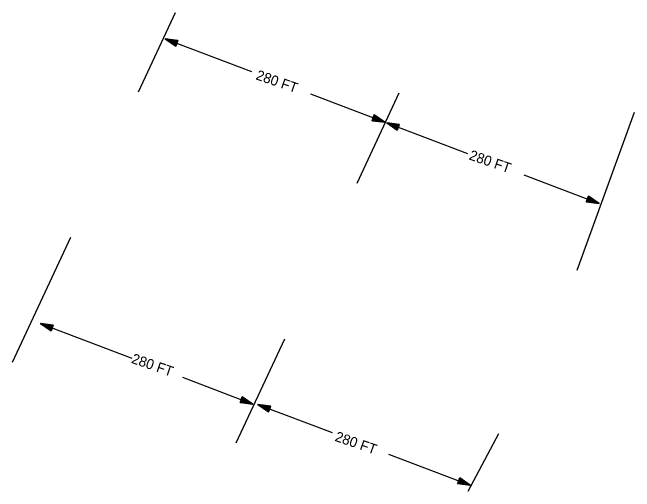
# Model space of a CAD drawing. Extents: x 1638506 to 1658005, y 834807 to 846788.
# Drawn here: x 1638846 to 1639584, y 840006 to 840574 of the extents above; entities that cross this region are included whole.
import ezdxf

# ---------------------------------------------------------------- set-up
doc = ezdxf.new("R2010")
doc.units = 0
doc.layers.add('Default', color=7, linetype='Continuous')

msp = doc.modelspace()

# ---------------------------------------------------------------- linework, layer by layer
at = {"layer": 'Default'}
for p, q in [((1638995.77, 840480.13), (1639039.69, 840574.45)), ((1639027.46, 840542.98), (1639129.82, 840504.15)), ((1639199.65, 840477.66), (1639287.86, 840444.19)), ((1639255.18, 840371.66), (1639305.11, 840478.9)), ((1639516.11, 840268.32), (1639584.12, 840455.99)), ((1639290.17, 840443.32), (1639386.13, 840406.91)), ((1639452.93, 840381.57), (1639542.02, 840347.78)), ((1638846.32, 840159.16), (1638915.51, 840307.75)), ((1638879.63, 840205.15), (1638987.93, 840164.07)), ((1639111.75, 840063.61), (1639169.28, 840187.17)), ((1639047.89, 840141.32), (1639131.48, 840109.61)), ((1639137.47, 840108.98), (1639225.32, 840075.66)), ((1639422.88, 840074.06), (1639386.35, 840005.71)), ((1639292.23, 840050.27), (1639389.31, 840013.44))]:
    msp.add_line(p, q, dxfattribs=at)
for points in [[(1639041.29, 840537.73), (1639041.03, 840537.04), (1639027.46, 840542.98), (1639040.78, 840536.39), (1639040.52, 840535.7), (1639027.46, 840542.98), (1639040.26, 840535.01), (1639040, 840534.32), (1639027.46, 840542.98), (1639042.56, 840541.21), (1639042.34, 840540.5), (1639027.46, 840542.98), (1639042.03, 840539.82), (1639041.82, 840539.11), (1639027.46, 840542.98), (1639041.55, 840538.42), (1639040, 840534.32), (1639042.56, 840541.21), (1639027.46, 840542.98), (1639040, 840534.32)], [(1639274.03, 840449.44), (1639274.29, 840450.13), (1639287.86, 840444.19), (1639274.54, 840450.78), (1639274.8, 840451.47), (1639287.86, 840444.19), (1639275.06, 840452.16), (1639275.32, 840452.85), (1639287.86, 840444.19), (1639272.76, 840445.96), (1639272.98, 840446.67), (1639287.86, 840444.19), (1639273.29, 840447.35), (1639273.5, 840448.06), (1639287.86, 840444.19), (1639273.77, 840448.75), (1639275.32, 840452.85), (1639272.76, 840445.96), (1639287.86, 840444.19), (1639275.32, 840452.85)], [(1639304.01, 840438.07), (1639303.75, 840437.38), (1639290.17, 840443.32), (1639303.5, 840436.73), (1639303.24, 840436.04), (1639290.17, 840443.32), (1639302.98, 840435.35), (1639302.71, 840434.65), (1639290.17, 840443.32), (1639305.27, 840441.54), (1639305.06, 840440.83), (1639290.17, 840443.32), (1639304.75, 840440.16), (1639304.53, 840439.45), (1639290.17, 840443.32), (1639304.27, 840438.76), (1639302.71, 840434.65), (1639305.27, 840441.54), (1639290.17, 840443.32), (1639302.71, 840434.65)], [(1639528.19, 840353.02), (1639528.45, 840353.72), (1639542.02, 840347.78), (1639528.69, 840354.36), (1639528.96, 840355.05), (1639542.02, 840347.78), (1639529.22, 840355.74), (1639529.48, 840356.44), (1639542.02, 840347.78), (1639526.92, 840349.55), (1639527.14, 840350.26), (1639542.02, 840347.78), (1639527.44, 840350.93), (1639527.66, 840351.64), (1639542.02, 840347.78), (1639527.92, 840352.33), (1639529.48, 840356.44), (1639526.92, 840349.55), (1639542.02, 840347.78), (1639529.48, 840356.44)], [(1638893.47, 840199.91), (1638893.21, 840199.21), (1638879.63, 840205.15), (1638892.96, 840198.57), (1638892.7, 840197.88), (1638879.63, 840205.15), (1638892.44, 840197.18), (1638892.17, 840196.49), (1638879.63, 840205.15), (1638894.73, 840203.38), (1638894.52, 840202.67), (1638879.63, 840205.15), (1638894.21, 840202), (1638893.99, 840201.29), (1638879.63, 840205.15), (1638893.73, 840200.6), (1638892.17, 840196.49), (1638894.73, 840203.38), (1638879.63, 840205.15), (1638892.17, 840196.49)], [(1639117.64, 840114.86), (1639117.91, 840115.55), (1639131.48, 840109.61), (1639118.15, 840116.2), (1639118.41, 840116.89), (1639131.48, 840109.61), (1639118.68, 840117.58), (1639118.94, 840118.27), (1639131.48, 840109.61), (1639116.38, 840111.39), (1639116.6, 840112.09), (1639131.48, 840109.61), (1639116.9, 840112.77), (1639117.12, 840113.48), (1639131.48, 840109.61), (1639117.38, 840114.17), (1639118.94, 840118.27), (1639116.38, 840111.39), (1639131.48, 840109.61), (1639118.94, 840118.27)], [(1639151.3, 840103.73), (1639151.04, 840103.04), (1639137.47, 840108.98), (1639150.79, 840102.4), (1639150.53, 840101.71), (1639137.47, 840108.98), (1639150.27, 840101.01), (1639150.01, 840100.32), (1639137.47, 840108.98), (1639152.57, 840107.21), (1639152.35, 840106.5), (1639137.47, 840108.98), (1639152.04, 840105.83), (1639151.83, 840105.12), (1639137.47, 840108.98), (1639151.56, 840104.43), (1639150.01, 840100.32), (1639152.57, 840107.21), (1639137.47, 840108.98), (1639150.01, 840100.32)], [(1639375.48, 840018.69), (1639375.74, 840019.38), (1639389.31, 840013.44), (1639375.99, 840020.03), (1639376.25, 840020.72), (1639389.31, 840013.44), (1639376.51, 840021.41), (1639376.77, 840022.1), (1639389.31, 840013.44), (1639374.21, 840015.21), (1639374.43, 840015.92), (1639389.31, 840013.44), (1639374.74, 840016.6), (1639374.95, 840017.31), (1639389.31, 840013.44), (1639375.22, 840018), (1639376.77, 840022.1), (1639374.21, 840015.21), (1639389.31, 840013.44), (1639376.77, 840022.1)]]:
    msp.add_lwpolyline(points, dxfattribs=at)

# ---------------------------------------------------------------- texts
for p in [(1639134.18, 840495.23), (1639386.94, 840400.16), (1638986.49, 840158.66), (1639227.83, 840066.12)]:
    msp.add_text('280 FT', height=12, rotation=340.96698, dxfattribs=at).set_placement(p)

doc.saveas('drawing.dxf')
